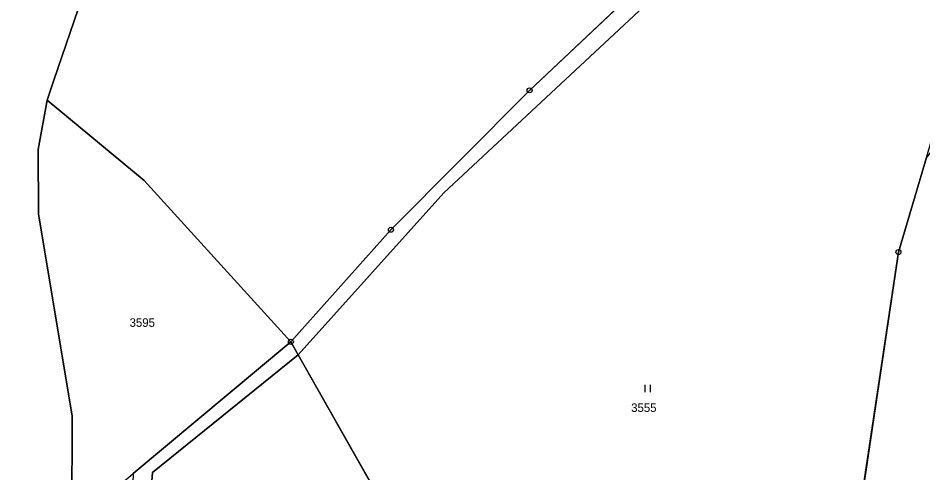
# Model space of a CAD drawing. Extents: x -689422 to -685210, y -987725 to -982160.
# Drawn here: x -688519.4 to -688338.6, y -984406.7 to -984315.8 of the extents above; entities that cross this region are included whole.
import ezdxf

# ---------------------------------------------------------------- set-up
doc = ezdxf.new("R2010")
doc.units = 0
for name, color, linetype in [('KN_Hranice obce', 7, 'Continuous'), ('KN_Hranice_katastrální území', 7, 'Continuous'), ('KN_Hranice_parcel', 7, 'Continuous'), ('KN_Parcelni cisla', 7, 'Continuous'), ('KN_Polygon parcely', 7, 'Continuous'), ('KN_POZEMKY_ORNA PUDA', 7, 'Continuous'), ('KN_POZEMKY_OSTATNI PLOCHA', 7, 'Continuous'), ('KN_POZEMKY_TTP', 7, 'Continuous'), ('KN_VYUZITI_17_ostatni plocha_ostatni komunikace', 7, 'Continuous'), ('KN_Značky bodu BP', 7, 'Continuous'), ('KN_Značky kultur', 7, 'Continuous')]:
    doc.layers.add(name, color=color, linetype=linetype)

msp = doc.modelspace()

# ---------------------------------------------------------------- linework, layer by layer
at = {"layer": 'KN_Hranice obce'}
msp.add_lwpolyline([(-688496.96, -984283.24), (-688512.25, -984328.23), (-688513.61, -984332.24), (-688515.42, -984342.1), (-688515.34, -984354.96), (-688508.59, -984395.38), (-688508.63, -984401.8), (-688508.67, -984408.61), (-688508.68, -984410.07), (-688511.07, -984418.68), (-688514.19, -984429.94), (-688516.06, -984436.68), (-688519.42, -984451.17), (-688518.03, -984456.68), (-688516.68, -984462), (-688512.97, -984476.55), (-688510.04, -984490.37), (-688507.09, -984504.27), (-688505.49, -984511.8), (-688502.99, -984530.58), (-688502.72, -984532.63), (-688500.95, -984546)], dxfattribs=at)
at = {"layer": 'KN_Hranice_katastrální území'}
msp.add_lwpolyline([(-688496.96, -984283.24), (-688512.25, -984328.23), (-688513.61, -984332.24), (-688515.42, -984342.1), (-688515.34, -984354.96), (-688508.59, -984395.38), (-688508.63, -984401.8), (-688508.67, -984408.61), (-688508.68, -984410.07), (-688511.07, -984418.68), (-688514.19, -984429.94), (-688516.06, -984436.68), (-688519.42, -984451.17), (-688518.03, -984456.68), (-688516.68, -984462), (-688512.97, -984476.55), (-688510.04, -984490.37), (-688507.09, -984504.27), (-688505.49, -984511.8), (-688502.99, -984530.58), (-688502.72, -984532.63), (-688500.95, -984546)], dxfattribs=at)
at = {"layer": 'KN_Hranice_parcel'}
for p, q in [((-688496.96, -984283.24), (-688512.25, -984328.23)), ((-688512.25, -984328.23), (-688513.61, -984332.24)), ((-688337.85, -984343.69), (-688343.44, -984362.56)), ((-688343.44, -984362.56), (-688352.68, -984424.32)), ((-688464.89, -984380.5), (-688496.44, -984406.77)), ((-688463.41, -984383.11), (-688464.89, -984380.5)), ((-688463.41, -984383.11), (-688418.64, -984462.03)), ((-688508.59, -984395.38), (-688508.63, -984401.8)), ((-688508.63, -984401.8), (-688508.67, -984408.61))]:
    msp.add_line(p, q, dxfattribs=at)
for points in [[(-688333.33, -984258.62), (-688350.63, -984272.75), (-688434.3, -984350.74), (-688463.41, -984383.11)], [(-688464.89, -984380.5), (-688444.89, -984358.12), (-688417.17, -984330.26), (-688386.77, -984301.57), (-688352.42, -984270.6)], [(-688513.61, -984332.24), (-688515.42, -984342.1), (-688515.34, -984354.96), (-688508.59, -984395.38)], [(-688513.61, -984332.24), (-688494.24, -984348.25), (-688464.89, -984380.5)], [(-688463.41, -984383.11), (-688492.58, -984406.59), (-688494.26, -984428.63), (-688474.22, -984515.84), (-688478.15, -984518.75)]]:
    msp.add_lwpolyline(points, dxfattribs=at)
at = {"layer": 'KN_Polygon parcely'}
for points in [[(-688386.77, -984301.57), (-688352.42, -984270.6), (-688410.85, -984208.17), (-688435.82, -984184.61), (-688440.98, -984195.15), (-688451.12, -984212.71), (-688479.92, -984241.13), (-688491.32, -984254.62), (-688493.88, -984265.86), (-688496.96, -984283.24), (-688512.25, -984328.23), (-688513.61, -984332.24), (-688494.24, -984348.25), (-688464.89, -984380.5), (-688444.89, -984358.12), (-688417.17, -984330.26)], [(-688333.33, -984258.62), (-688319.09, -984245.01), (-688320.86, -984242.81), (-688335.25, -984256.31), (-688352.42, -984270.6), (-688386.77, -984301.57), (-688417.17, -984330.26), (-688444.89, -984358.12), (-688464.89, -984380.5), (-688463.41, -984383.11), (-688434.3, -984350.74), (-688350.63, -984272.75)], [(-688310.66, -984285.19), (-688333.33, -984258.62), (-688350.63, -984272.75), (-688434.3, -984350.74), (-688463.41, -984383.11), (-688418.64, -984462.03), (-688397.47, -984502.66), (-688382.21, -984494.98), (-688365.99, -984484.95), (-688344.22, -984485.07), (-688352.68, -984424.32), (-688343.44, -984362.56), (-688337.85, -984343.69), (-688332.15, -984324.44), (-688319.79, -984300.23)], [(-688292.34, -984380.43), (-688282.43, -984362), (-688306.76, -984341.99), (-688326.83, -984319.43), (-688335.94, -984341.28), (-688337.85, -984343.69), (-688343.44, -984362.56), (-688352.68, -984424.32), (-688344.22, -984485.07), (-688327.57, -984485.22), (-688307.61, -984427.45)], [(-688515.42, -984342.1), (-688515.34, -984354.96), (-688508.59, -984395.38), (-688508.63, -984401.8), (-688508.67, -984408.61), (-688506.85, -984413.09), (-688505.3, -984411.07), (-688504.07, -984413.23), (-688496.44, -984406.77), (-688464.89, -984380.5), (-688494.24, -984348.25), (-688513.61, -984332.24)], [(-688464.89, -984380.5), (-688496.44, -984406.77), (-688497.12, -984428.57), (-688478.15, -984518.75), (-688474.22, -984515.84), (-688494.26, -984428.63), (-688492.58, -984406.59), (-688463.41, -984383.11)], [(-688494.26, -984428.63), (-688474.22, -984515.84), (-688478.15, -984518.75), (-688483.99, -984522.61), (-688481.65, -984529.01), (-688447.23, -984524.37), (-688411.14, -984514.73), (-688397.47, -984502.66), (-688418.64, -984462.03), (-688463.41, -984383.11), (-688492.58, -984406.59)]]:
    msp.add_lwpolyline(points, close=True, dxfattribs=at)
at = {"layer": 'KN_POZEMKY_ORNA PUDA'}
for p, q in [((-688512.25, -984328.23), (-688496.96, -984283.24)), ((-688386.77, -984301.57), (-688417.17, -984330.26)), ((-688513.61, -984332.24), (-688512.25, -984328.23)), ((-688417.17, -984330.26), (-688444.89, -984358.12)), ((-688515.42, -984342.1), (-688513.61, -984332.24)), ((-688494.24, -984348.25), (-688513.61, -984332.24)), ((-688513.61, -984332.24), (-688494.24, -984348.25)), ((-688515.34, -984354.96), (-688515.42, -984342.1)), ((-688464.89, -984380.5), (-688494.24, -984348.25)), ((-688494.24, -984348.25), (-688464.89, -984380.5)), ((-688508.59, -984395.38), (-688515.34, -984354.96)), ((-688444.89, -984358.12), (-688464.89, -984380.5)), ((-688464.89, -984380.5), (-688496.44, -984406.77)), ((-688508.63, -984401.8), (-688508.59, -984395.38)), ((-688508.67, -984408.61), (-688508.63, -984401.8))]:
    msp.add_line(p, q, dxfattribs=at)
at = {"layer": 'KN_POZEMKY_OSTATNI PLOCHA'}
for p, q in [((-688350.63, -984272.75), (-688434.3, -984350.74)), ((-688417.17, -984330.26), (-688386.77, -984301.57)), ((-688444.89, -984358.12), (-688417.17, -984330.26)), ((-688434.3, -984350.74), (-688463.41, -984383.11)), ((-688464.89, -984380.5), (-688444.89, -984358.12)), ((-688496.44, -984406.77), (-688464.89, -984380.5)), ((-688463.41, -984383.11), (-688464.89, -984380.5)), ((-688464.89, -984380.5), (-688463.41, -984383.11)), ((-688463.41, -984383.11), (-688492.58, -984406.59)), ((-688492.58, -984406.59), (-688494.26, -984428.63))]:
    msp.add_line(p, q, dxfattribs=at)
at = {"layer": 'KN_POZEMKY_TTP'}
for p, q in [((-688434.3, -984350.74), (-688350.63, -984272.75)), ((-688343.44, -984362.56), (-688337.85, -984343.69)), ((-688337.85, -984343.69), (-688343.44, -984362.56)), ((-688463.41, -984383.11), (-688434.3, -984350.74)), ((-688352.68, -984424.32), (-688343.44, -984362.56)), ((-688343.44, -984362.56), (-688352.68, -984424.32)), ((-688492.58, -984406.59), (-688463.41, -984383.11)), ((-688418.64, -984462.03), (-688463.41, -984383.11)), ((-688463.41, -984383.11), (-688418.64, -984462.03)), ((-688494.26, -984428.63), (-688492.58, -984406.59))]:
    msp.add_line(p, q, dxfattribs=at)
at = {"layer": 'KN_VYUZITI_17_ostatni plocha_ostatni komunikace'}
for p, q in [((-688350.63, -984272.75), (-688434.3, -984350.74)), ((-688417.17, -984330.26), (-688386.77, -984301.57)), ((-688444.89, -984358.12), (-688417.17, -984330.26)), ((-688434.3, -984350.74), (-688463.41, -984383.11)), ((-688464.89, -984380.5), (-688444.89, -984358.12)), ((-688496.44, -984406.77), (-688464.89, -984380.5)), ((-688463.41, -984383.11), (-688464.89, -984380.5)), ((-688464.89, -984380.5), (-688463.41, -984383.11)), ((-688463.41, -984383.11), (-688492.58, -984406.59)), ((-688492.58, -984406.59), (-688494.26, -984428.63))]:
    msp.add_line(p, q, dxfattribs=at)
at = {"layer": 'KN_Značky bodu BP'}
for centre, radius in [((-688417.17, -984330.26), 0.5), ((-688417.17, -984330.26), 0.0303), ((-688444.89, -984358.12), 0.5), ((-688444.89, -984358.12), 0.0303), ((-688343.44, -984362.56), 0.5), ((-688343.44, -984362.56), 0.0303), ((-688464.89, -984380.5), 0.5), ((-688464.89, -984380.5), 0.0303)]:
    msp.add_circle(centre, radius, dxfattribs=at)
at = {"layer": 'KN_Značky kultur'}
for p, q in [((-688394.04, -984390.56), (-688394.04, -984389.06)), ((-688393.04, -984390.56), (-688393.04, -984389.06))]:
    msp.add_line(p, q, dxfattribs=at)

# ---------------------------------------------------------------- texts
at = {"layer": 'KN_Parcelni cisla'}
for s, p in [('3595', (-688497.13, -984377.5)), ('3555', (-688396.87, -984394.51))]:
    msp.add_text(s, height=1.7, dxfattribs=at).set_placement(p)

doc.saveas('drawing.dxf')
